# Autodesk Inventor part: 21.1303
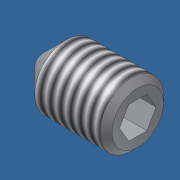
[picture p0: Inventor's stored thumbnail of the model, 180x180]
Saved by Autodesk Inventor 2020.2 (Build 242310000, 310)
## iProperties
Created: 2006-02
Part Number: 21.1303
Material: Steel, Mild
Description: SET SCREW M8X14 WITH CONE POINT
Document SubType Name: Modeling
Standard: DIN 914
Designer: Andy Moles
Standards Organization: DIN
Language: en-US
Size Designation: M8 x 12
Categories: <MemberInstance><Categories><Category DisplayName="Fasteners" InternalName="e4da775c-781d-43d5-af7c-5136215cf5a6" Mnemonic="FSTN"><Category DisplayName="Bolts"
Mass: 4.20865 g
Surface Area: 4.57509 cm^2
Volume: 0.535451 cm^3
Density: 7.86 g/cm^3
Vendor: S
Appearance: Zinc
Author: Andy Moles
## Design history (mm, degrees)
sketch "Sketch1"
  geometry: L1 (0, 0)-(7.667, 0); L2 (14, 2.309)-(14, 4); L3 (14, 4)-(0, 4); L4 (14, 2.309)-(9, 2.309); L5 (9, 2.309)-(7.667, 0); L6 (0, -0.4)-(0, 5.2) reference; L7 (0, 4)-(0, 0)
  constraints: 13 end point, 3 parallel, 1 collinear, 1 perpendicular, 1 point on line
  dimensions: "d0" = 5 distance of L2.start L4.end (= INTI); "d1" = 60 deg angle of L5 L1; "d2" = 8 diameter of L3 L1 (= NND); "d3" = 4.6188 diameter of L4 L1 (= 1.1547 x SW); "d5" = 14 distance from line of L2 L3.end (= NLG)
revolve "Body" sketch "Sketch1" stored, may be unused: angle "d6" = 90 deg
sketch "Sketch2"
  geometry: L1 (-1.155, 2)-(1.155, 2); L2 (1.155, 2)-(2.309, 0); L3 (2.309, 0)-(1.155, -2); L4 (1.155, -2)-(-1.155, -2); L5 (-1.155, -2)-(-2.309, 0); L6 (-2.309, 0)-(-1.155, 2); 3 further points
  constraints: 12 end point, 1 coincident, 1 horizontal, 13 other
extrude "Slot" join sketch "Sketch2" taper "d7" = 0 deg; stored distance "d21" = 10
workaxis "Work Axis1"
workplane "Work Plane1"
body "Solid1"
feature "Thread" dims "d12" = 14 (= NLG), "d13" = 0
chamfer "Chamfer1" distance "d8" = 3 (computed from NND, SPD, FAWI); stored, may be unused: angle "d9" = 45 deg (= FAWI), second distance "d34" = 3 (computed from NND, SPD, FAWI)
chamfer "Chamfer2" distance "d10" = 0.76681 (= -0.5 x GD1 + 0.5 x NND); stored, may be unused: angle "d11" = 45 deg (= FAWI), second distance "d35" = 0.76681 (= -0.5 x GD1 + 0.5 x NND)
other parameters: "NND" = 8 [user parameter; used in 5 equation terms], "NLG" = 14 [user parameter; used in 2 equation terms], "INTI" = 5 [user parameter; used in 1 equation term], "FAWI" = 45 deg [user parameter; used in 4 equation terms], "SW" = 4 [user parameter; used in 2 equation terms], "GD1" = 6.46637 (= THREADDIA - 1.2269 x PTC) [user parameter; used in 2 equation terms], "d4" = 0, "FAWI1" = 45 deg [user parameter], "SPD" = 2 [user parameter; used in 2 equation terms], "d33" = 0, "d36" = 0, "GUL" = 0.76681 (= 0.61345 x PTC) [user parameter], "TPU" = 8 (computed from PTC) [user parameter], "TOA" = 30 deg [user parameter], "THREADDIA" = 8 [user parameter; used in 1 equation term], "PTC" = 1.25 [user parameter; used in 4 equation terms], "GAL" = 0.76681 (= 0.61345 x PTC) [user parameter], "E0" = 4.62 (= 1.155 x SW) [user parameter]
